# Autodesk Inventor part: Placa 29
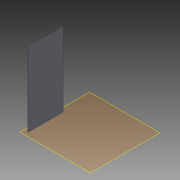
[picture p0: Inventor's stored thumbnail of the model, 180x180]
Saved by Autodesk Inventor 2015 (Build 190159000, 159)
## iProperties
Created: 2015-04
Part Number: Placa 29
Material: Generic
Document SubType Name: Modeling
Designer: suporte
Density: 1 g/cm^3
Appearance: Default
Author: suporte
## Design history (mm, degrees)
workplane "Work Plane1"
sketch "Sketch1"
  geometry: L1 (-800, -875)-(-900, -875) reference; L2 (-900, -875)-(-887.5, -875); L3 (-887.5, -875)-(-887.5, 125); L4 (-887.5, 125)-(-900, 125); L5 (-900, 125)-(-900, -875); 1 further point
  constraints: 8 end point, 2 parallel, 1 horizontal, 1 perpendicular
  dimensions: "d0" = 12.5 distance of L4.end L3.end; "d1" = 1000 distance of L3.end L2.end
extrude "Extrusion1" new body sketch "Sketch1" distance "d2" = 2100; taper "d3" = 0 deg
body "Solid1"
node "Reference1"
